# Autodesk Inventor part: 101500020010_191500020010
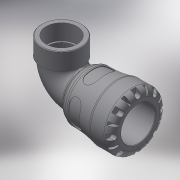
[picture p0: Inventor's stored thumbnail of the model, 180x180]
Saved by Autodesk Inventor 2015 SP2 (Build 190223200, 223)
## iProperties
Created: 2016-12
Part Number: 101500020010_191500020010
Material: Generic
Description: PLASSON 90° ELBOW WITH THREADED FEMALE OFFTAKE 20X1" SERIES 1
Document SubType Name: Modeling
Designer: KIM
Mass: 557.611 g
Surface Area: 990.043 cm^2
Volume: 557.611 cm^3
Density: 1 g/cm^3
Appearance: Default
Author: KIM
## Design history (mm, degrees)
derived "1015.ipt"
feature "Solid1::1015.ipt"
tag "TaggingFeature1"
body "Solid1"
other parameters: "d1" = 18.9, "d3" = 25, "d4" = 41, "d8" = 36.08, "d13" = 6.4, "d14" = 6.4, "d15" = 0, "d17" = 360 deg, "d19" = 8 deg, "d20" = 0.4, "d21" = 0.4, "d22" = 8 deg, "d24" = 0, "d26" = 360 deg, "d33" = 4.1, "d43" = 33.62, "d51" = 0.41, "d54" = 7, "d55" = 4.4, "d57" = 12.544, "d58" = 0, "d74" = 0, "d78" = 45, "d82" = 0.4, "d115" = 360 deg, "d207" = 90 deg, "d228" = 5.95, "d247" = 0.82, "d248" = 2.7, "d268" = 19.844, "d269" = 2.7, "d270" = 67, "d279" = 49, "d281" = 4.54365, "d294" = 30.291, "d295" = 21, "d296" = 23.1, "d297" = 27.2619, "d299" = 35.44047, "d300" = 27.2619, "d301" = 0, "d302" = 0, "d303" = -0.91023, "d306" = 0, "d307" = 9, "d308" = 8, "d310" = 3, "E_" = 41, "l_" = 45, "A_" = 67, "A_1" = 49, "l_2" = 21, "Rp_" = 30.291, "d9" = 8, "d11" = 41, "d12" = 25, "d298" = 39.3783
